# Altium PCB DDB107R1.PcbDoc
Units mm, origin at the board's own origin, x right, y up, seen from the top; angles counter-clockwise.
Board outline 117 x 54.5 mm, 4 copper layers (Top Layer, Layer 1, Layer 2, Bottom Layer); 23 components, 8 nets, 55 pads, 275 vias.
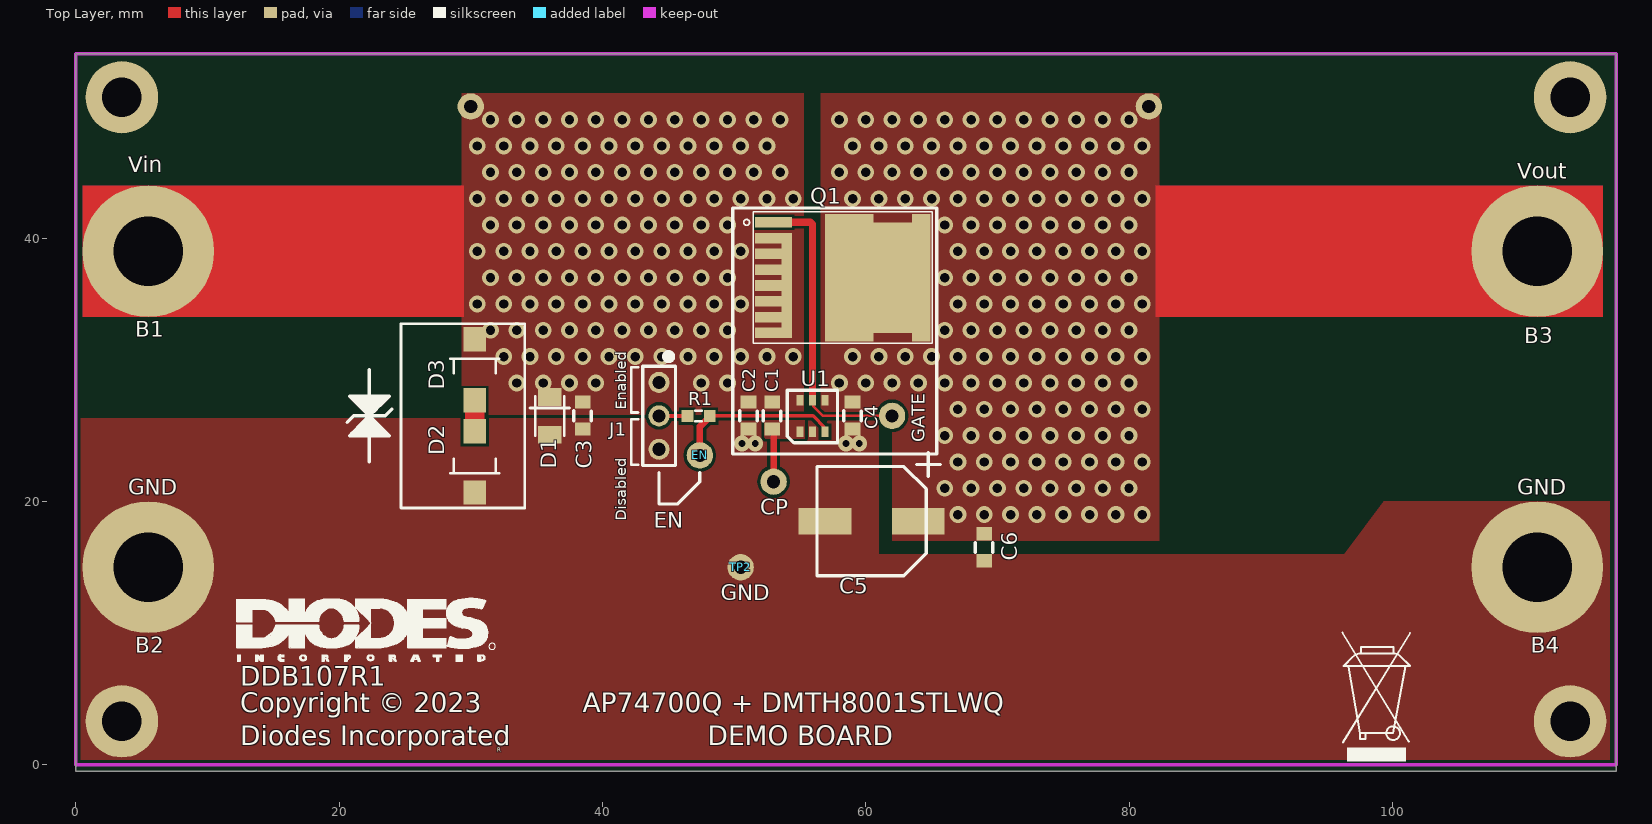
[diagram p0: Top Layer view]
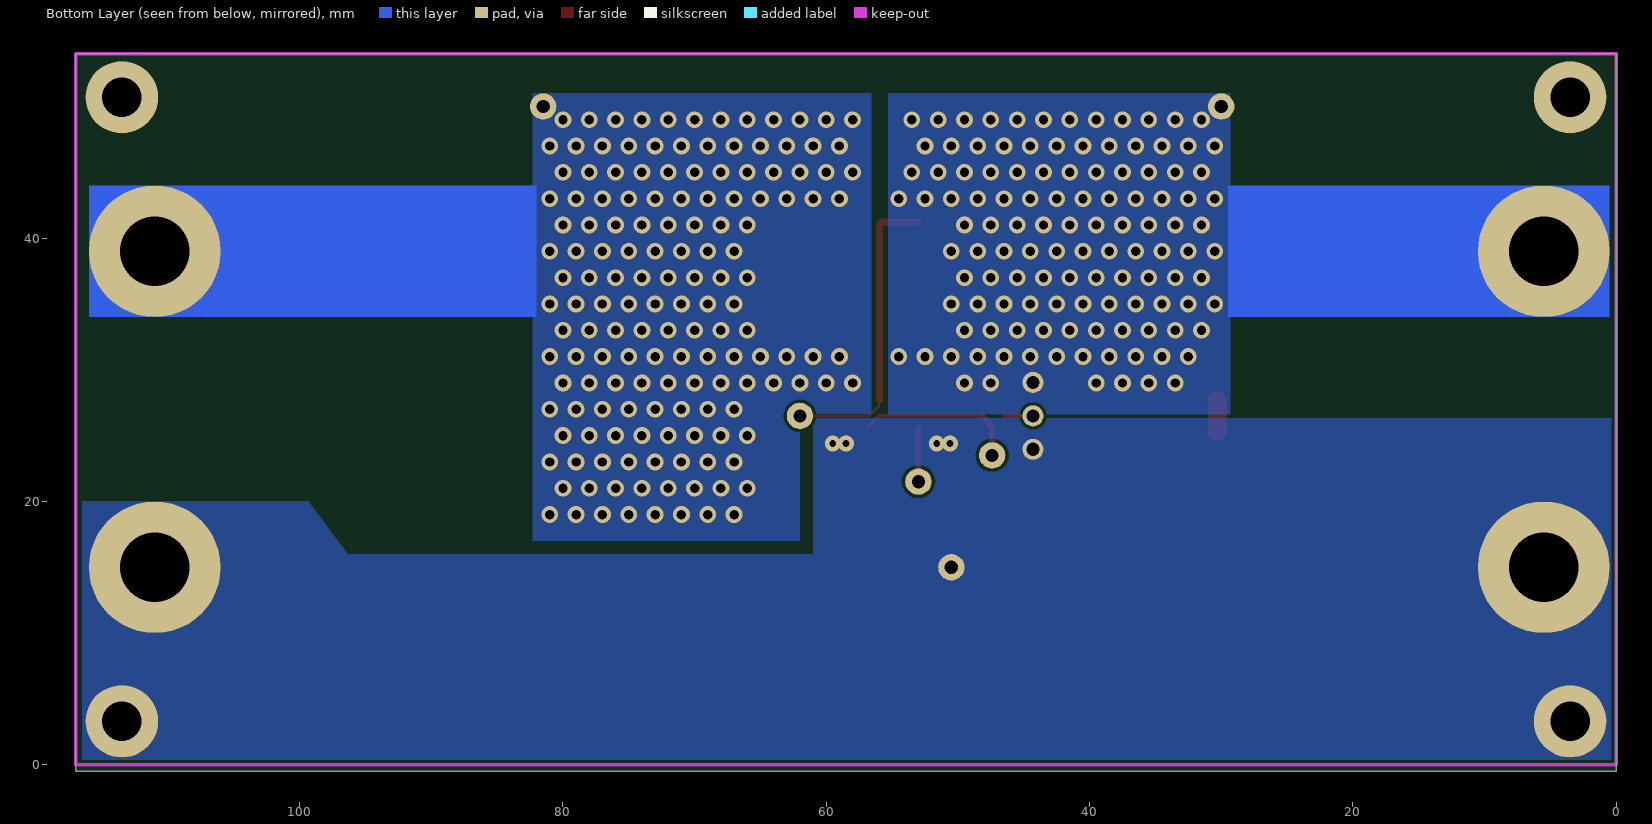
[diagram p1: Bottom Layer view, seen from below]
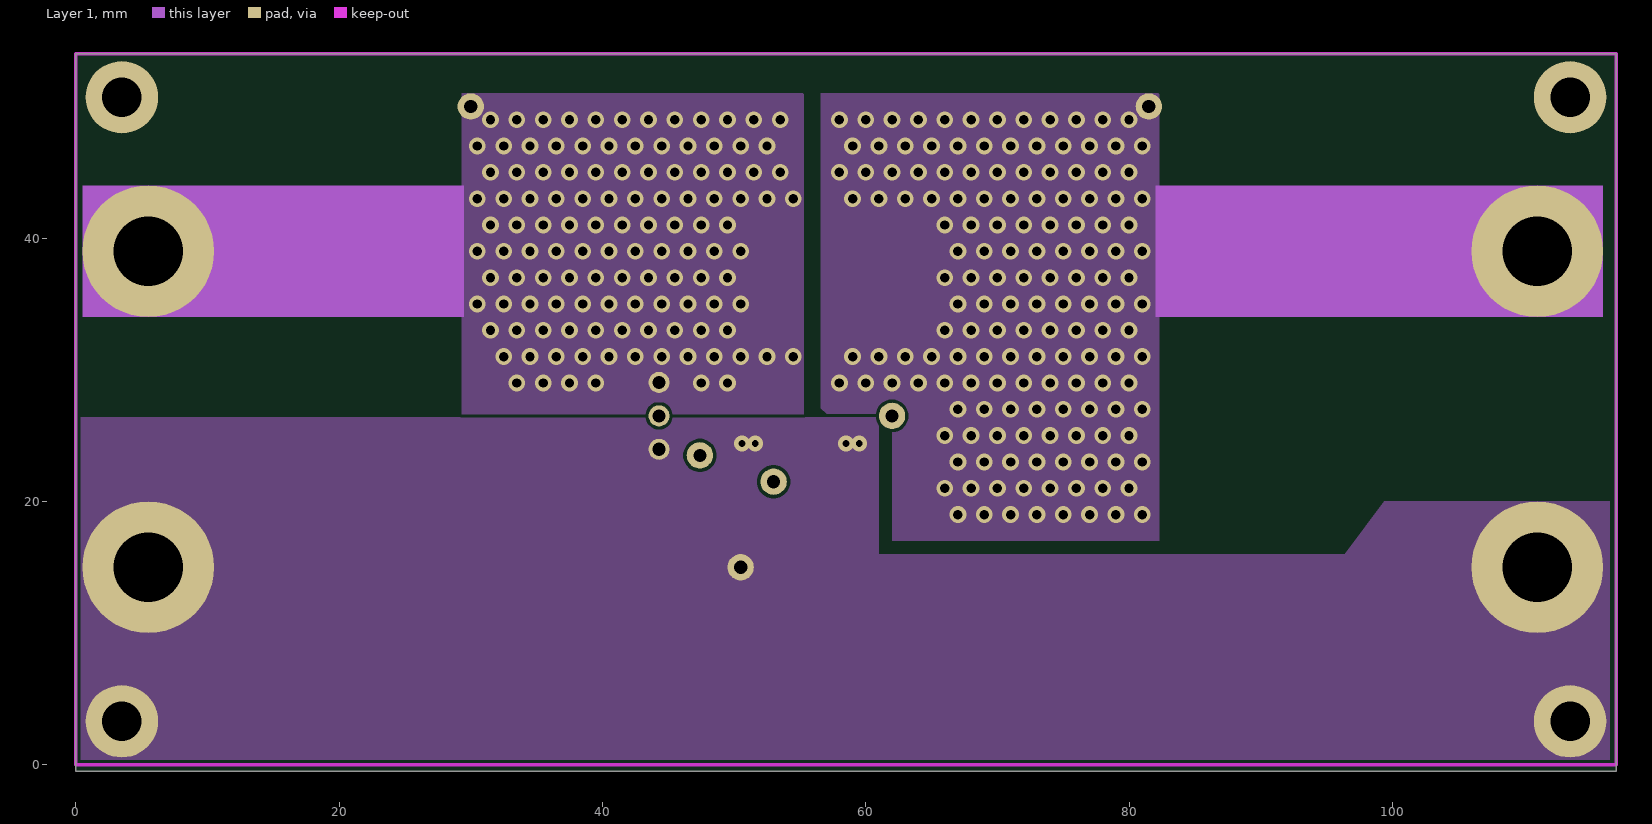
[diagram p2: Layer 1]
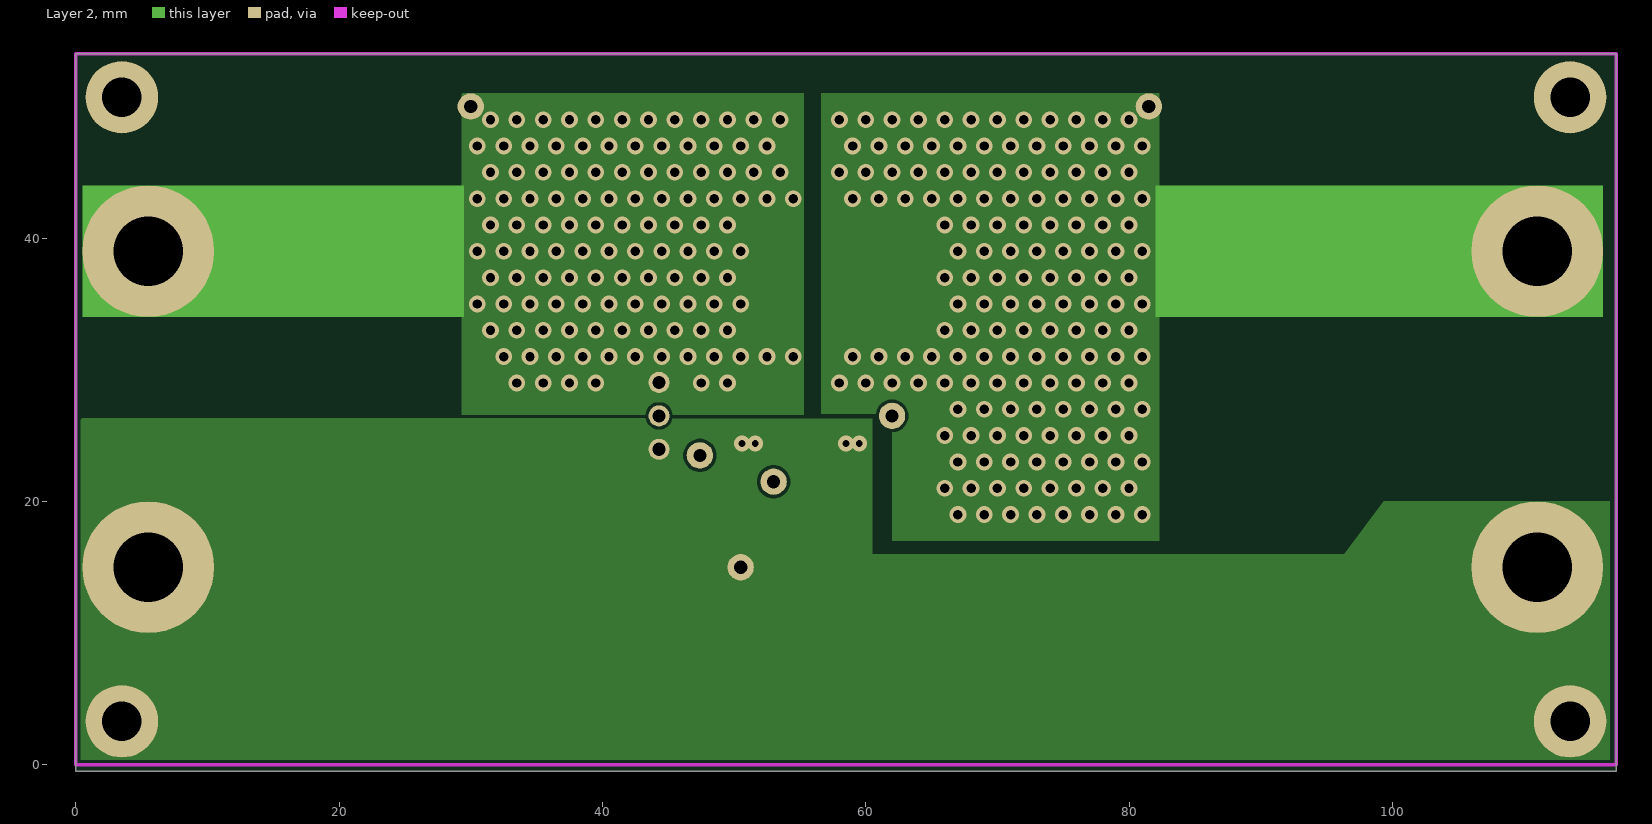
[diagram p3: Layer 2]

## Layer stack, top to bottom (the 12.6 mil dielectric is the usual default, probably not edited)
Top Solder: solder mask 0.0102, Solder Resist, Dk 3.5
Top Layer: signal copper 0.035
Dielectric 1: prepreg 0.32, FR-4, Dk 4.8
Layer 1: signal copper 0.035
Dielectric2: dielectric 0.32, FR-4, Dk 4.8
Layer 2: signal copper 0.035
Dielectric 3: prepreg 0.32, FR-4, Dk 4.8
Bottom Layer: signal copper 0.035
Bottom Solder: solder mask 0.0102, Solder Resist, Dk 3.5

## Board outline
0,54 117,54 117,-0.5 0,-0.5

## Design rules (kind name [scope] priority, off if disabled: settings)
Clearance Clearance_2 [(InNet('GND'))] p1: gap=0.25 ignorepadtopadclearanceinfootprint=FALSE except(0: Arc-Hole Track-Hole SMDPad-Hole THPad-Hole Via-Hole Fill-Hole Poly-Hole Region-Hole Text-Hole)
Clearance Clearance_1 [(IsPad AND OnLayer('Multi-Layer'))] p2: gap=0.25 ignorepadtopadclearanceinfootprint=FALSE except(0: Arc-Hole Track-Hole SMDPad-Hole THPad-Hole Via-Hole Fill-Hole Poly-Hole Region-Hole Text-Hole)
Clearance [All] p3: gap=0.2 ignorepadtopadclearanceinfootprint=FALSE except(0: Arc-Hole Track-Hole SMDPad-Hole THPad-Hole Via-Hole Fill-Hole Poly-Hole Region-Hole Text-Hole)
FabricationTestPointUsage TestPointUsage [All] p1: valid=0 allowmultiple=FALSE
FabricationTestpoint Testpoint [All] p1: side=3 testpointundercomponent=TRUE minsize=1.016 maxsize=2.54 preferedsize=1.524 minholesize=0 maxholesize=1.016 preferedholesize=0.813 testpointgrid=0.025 allowsidetop=TRUE allowsidebottom=TRUE usegrid=TRUE gridtolerance=0
HoleSize [All] p1: absolutevalues=TRUE maxlimit=10 minlimit=0.2 maxpercent=80.000 minpercent=20.000
PlaneClearance [All] p1: clearance=0.1
PolygonConnect [All] p1: connectstyle=Direct reliefconductorwidth=0.254 reliefentries=4 polygonreliefangle="90 Angle" airgapwidth=0.254
RoutingVias [All] p1: holewidth=0.711 width=1.27 viastyle="Through Hole" minholewidth=0.5 minwidth=0.5 maxholewidth=1.5 maxwidth=1.5
SolderMaskExpansion [All] p1: expansion=0.102 istentingtop=FALSE
Width [All] p1: maxlimit=10 minlimit=0.2 preferedwidth=0.254 minimp=50.000000 maximp=50.000000 favimp=50.000000
26 further rules are at their usual default settings.

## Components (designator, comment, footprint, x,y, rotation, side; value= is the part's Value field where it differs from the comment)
B1 "Banana Socket 4mm" "Banana Plug"#1 34,39 r0 top
B2 "Banana Socket 4mm" "Banana Plug"#2 34,14 r0 top
B3 "Banana Socket 4mm" "Banana Plug"#3 78,39 r0 top
B4 "Banana Socket 4mm" "Banana Plug"#4 78,14 r0 top
C1 "Capacitor" 0805 52.9,26.5 r90 top
C2 "Capacitor" 0805 51.1,26.5 r90 top
C3 "Capacitor" 0805 38.5,26.5 r90 top
C4 "Capacitor" 0805 59,26.5 r90 top
C5 "Capacitor" "Case F Cap" 60.45,18.5 r270 top
C6 "Capacitor" 0805 69,16.5 r90 top
CP "Test Point" TestPoint#1 53,21.5 r0 top
D1 "SMF4L30CAQ" SMF4Lxx(C)AQ 36,26.5 r90 top
D2 "P6SMAJ26ADFQ" P6SMAJxxADFQ 30.3,23 r90 top
D3 "P6SMAJ43ADFQ" P6SMAJxxADFQ 30.3,30 r270 top
EN "Test Point" TestPoint#1 47.4,23.5 r0 top
GATE "Test Point" TestPoint#2 58.5,26.5 r90 top
J1 "3W header" "0.1\" 3W" 44.3,26.5 r270 top
Q1 "DMTH8001STLWQ" PowerDI1012-8L 58.25,37 r0 top
R1 "Resistance" 0603 47.3,26.5 r0 top
TP2 "Test Point" TestPoint#1 50.5,15 r90 top
U1 "AP74700" SOT26 56,26.5 r0 top
Vin "Test Point" TestPoint#3 38,50 r90 top
Vout "Test Point" TestPoint#4 74.5,50 r90 top

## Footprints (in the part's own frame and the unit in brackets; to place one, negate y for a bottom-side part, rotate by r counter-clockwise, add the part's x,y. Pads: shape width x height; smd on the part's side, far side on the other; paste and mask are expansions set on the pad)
"0.1\" 3W" [mm]
  round 1.6 hole 1: 1(-2.54,0) 2(0,0) 3(2.54,0)
  silkscreen extent -4.75,-1.25 3.77,1.25, body extent -3.77,-1.25 3.77,1.25, height 8
0603 [mm]
  rect 0.9x0.9 smd: 1(-0.85,0) 2(0.85,0)
  silkscreen extent -0.25,-0.4 0.25,0.4, body extent -1.4,-0.55 1.4,0.55
0805 [mm]
  rect 1x1.2 smd: 1(-1,0) 2(1.05,0)
  silkscreen extent -0.38,-0.65 0.38,0.67, body extent -1.65,-0.7 1.65,0.7
"Banana Plug"#1 [mm]
  round 10 hole 5.3: 1(-28.5,0)
"Banana Plug"#2 [mm]
  round 10 hole 5.3: 1(-28.5,1)
"Banana Plug"#3 [mm]
  round 10 hole 5.3: 1(33,0)
"Banana Plug"#4 [mm]
  round 10 hole 5.3: 1(33,1)
"Case F Cap" [mm]
  rect 2x4 smd: 1(0,3.55) 2(0,-3.55)
  silkscreen extent -5.2,-4.15 4.15,5.2, body extent -4.15,-4.15 4.15,4.15
P6SMAJxxADFQ [mm]
  rect 1.85x1.7 smd: 0(-2.325,0) 1(2.325,0)
  silkscreen extent -0.85,-1.85 0.25,1.85, body extent -2.3,-1.47 2.3,1.47
PowerDI1012-8L [mm]
  rect 2.8x0.8 smd: 1(-5.25,4.2) 2(-5.25,3) 3(-5.25,1.8) 4(-5.25,0.6) 5(-5.25,-0.6) 6(-5.25,-1.8) 7(-5.25,-3) 8(-5.25,-4.2)
  rect 0.8x8 smd: 5(-4.25,-0.6)
  rect 3.7x9.7 smd: 9(0.5,0)
  rect 3.2x8.4 smd: 10(3.75,0)
  rect 1.4x9.7 smd: 11(5.95,0)
  silkscreen extent -7.52,-5 6.8,5
SMF4Lxx(C)AQ [mm]
  rect 1.34x1.8 smd: 0(1.43,0) 1(-1.43,0)
  silkscreen extent -1.5,-1.5 1.5,1.5, body extent -1.45,-1 1.45,1
SOT26 [mm]
  rect 0.55x0.8 smd: 1(-1.002,-1.198) 2(-0.052,-1.198) 3(0.898,-1.198) 4(0.898,1.202) 5(-0.052,1.202) 6(-1.002,1.202)
  silkscreen extent -1.95,-2.05 1.85,1.95, body extent -1.55,-1.4 1.45,1.4
TestPoint#1 [mm]
  round 2 hole 1: 1(0,0)
TestPoint#2 [mm]
  round 2 hole 1: 1(0,-3.5)
TestPoint#3 [mm]
  round 2 hole 1: 1(0,8)
TestPoint#4 [mm]
  round 2 hole 1: 1(0,-7)

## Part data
D1: library part SMF4Lxx(C)AQ, "TVS Device"
D2 D3: library part P6SMAJxxADFQ, "TVS Device"
Q1: library part PowerDI1012-8L

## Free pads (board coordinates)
  round 5.5 hole 3: 0(3.5,3.3) 0(3.5,50.7) 0(113.5,3.3) 0(113.5,50.7)

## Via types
v1: diameter 1.27, hole 0.711, Top Layer to Bottom Layer, 271 vias
v2: diameter 1.2, hole 0.5, Top Layer to Bottom Layer, tented both sides, 4 vias

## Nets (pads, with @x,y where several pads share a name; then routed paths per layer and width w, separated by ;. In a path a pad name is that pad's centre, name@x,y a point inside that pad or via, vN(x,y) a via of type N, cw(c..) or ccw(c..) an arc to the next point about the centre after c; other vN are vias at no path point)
GND: B2.1 B4.1 C2.1 C3.1 C4.1 C5.2 C6.1 D1.1 D2.0 J1.3 pad.0@3.5,3.3 pad.0@113.5,3.3 TP2.1 U1.2
  other v2: 50.6,24.4 51.6,24.4 58.5,24.4 59.5,24.4
NetC1_1: C1.1 CP.1 U1.1 | length 4
  Top Layer w0.5: CP.1 C1.1@53,25.5
NetD2_1: D2.1 D3.1 | length 2.4
  Top Layer w1.5: D2.1 D3.1
NetEN_1: EN.1 R1.2 U1.3 | length 12.4
  Top Layer w0.25: R1.2@48.2,26.5 56,26.5 U1.3@56.899,25.602
  Top Layer w0.5: EN.1 47.4,25.7 R1.2@48.2,26.5
NetGATE_1: GATE.1 Q1.1 U1.5 | length 22.8
  Top Layer w0.2: U1.5@56,27.4 56,27.25 56.75,26.5 GATE.1
  Top Layer w0.55: Q1.1 55.8,41.2 55.949,41.052 U1.5
NetJ1_2: J1.2 R1.1 | length 2.2
  Top Layer w0.3: J1.2 R1.1@46.5,26.5
VIN: B1.1 C1.2 C2.2 C3.2 D1.0 D3.0 J1.1 Q1.2 Q1.3 Q1.4 Q1.5 Q1.6 Q1.7 Q1.8 U1.6 Vin.1
  other v1: 33.5,29 35.5,29 37.5,29 39.5,29 47.5,29 49.5,29 32.5,31 34.5,31 36.5,31 38.5,31 40.5,31 42.5,31 44.5,31 46.5,31 48.5,31 50.5,31 52.5,31 54.5,31 31.5,33 33.5,33 35.5,33 37.5,33 39.5,33 41.5,33 43.5,33 45.5,33 47.5,33 49.5,33 30.5,35 32.5,35 34.5,35 36.5,35 38.5,35 40.5,35 42.5,35 44.5,35 46.5,35 48.5,35 50.5,35 31.5,37 33.5,37 35.5,37 37.5,37 39.5,37 41.5,37 43.5,37 45.5,37 47.5,37 49.5,37 30.5,39 32.5,39 34.5,39 36.5,39 38.5,39 40.5,39 42.5,39 44.5,39 46.5,39 48.5,39 50.5,39 31.5,41 33.5,41 35.5,41 37.5,41 39.5,41 41.5,41 43.5,41 45.5,41 47.5,41 49.5,41 30.5,43 32.5,43 34.5,43 36.5,43 38.5,43 40.5,43 42.5,43 44.5,43 46.5,43 48.5,43 50.5,43 52.5,43 54.5,43 31.5,45 33.5,45 35.5,45 37.5,45 39.5,45 41.5,45 43.5,45 45.5,45 47.5,45 49.5,45 51.5,45 53.5,45 30.5,47 32.5,47 34.5,47 36.5,47 38.5,47 40.5,47 42.5,47 44.5,47 46.5,47 48.5,47 50.5,47 52.5,47 31.5,49 33.5,49 35.5,49 37.5,49 39.5,49 41.5,49 43.5,49 45.5,49 47.5,49 49.5,49 51.5,49 53.5,49
VOUT: B3.1 C4.2 C5.1 C6.2 Q1.9 Q1.10 Q1.11 U1.4 Vout.1
  other v1: 67,19 69,19 71,19 73,19 75,19 77,19 79,19 81,19 66,21 68,21 70,21 72,21 74,21 76,21 78,21 80,21 67,23 69,23 71,23 73,23 75,23 77,23 79,23 81,23 66,25 68,25 70,25 72,25 74,25 76,25 78,25 80,25 67,27 69,27 71,27 73,27 75,27 77,27 79,27 81,27 58,29 60,29 62,29 64,29 66,29 68,29 70,29 72,29 74,29 76,29 78,29 80,29 59,31 61,31 63,31 65,31 67,31 69,31 71,31 73,31 75,31 77,31 79,31 81,31 66,33 68,33 70,33 72,33 74,33 76,33 78,33 80,33 67,35 69,35 71,35 73,35 75,35 77,35 79,35 81,35 66,37 68,37 70,37 72,37 74,37 76,37 78,37 80,37 67,39 69,39 71,39 73,39 75,39 77,39 79,39 81,39 66,41 68,41 70,41 72,41 74,41 76,41 78,41 80,41 59,43 61,43 63,43 65,43 67,43 69,43 71,43 73,43 75,43 77,43 79,43 81,43 58,45 60,45 62,45 64,45 66,45 68,45 70,45 72,45 74,45 76,45 78,45 80,45 59,47 61,47 63,47 65,47 67,47 69,47 71,47 73,47 75,47 77,47 79,47 81,47 58,49 60,49 62,49 64,49 66,49 68,49 70,49 72,49 74,49 76,49 78,49 80,49

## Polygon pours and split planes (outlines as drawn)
GND on Top Layer "Top Layer-No Net" (solid, pour order 1004): 0,26.3 0,-0.105 116.5,-0.105 116.5,20 99.349,20 96.349,16 61,16 61,26.3
VIN on Top Layer "Top Layer-No Net" (solid, pour order 1003): 55.304,26.6 29.3,26.6 29.3,51 55.304,51
VOUT on Top Layer "Top Layer-No Net" (solid, pour order 1002): 56.6,26.65 56.6,51 82.3,51 82.3,17 62,17 62,26.65
NetC1_1 on Top Layer "Top Layer-No Net" (solid, pour order 1001): 55.375,26.2 52.3,26.2 52.3,24.775 55.375,24.775
GND on Bottom Layer "Top Layer-No Net" (solid, pour order 1005): 0,26.3 61,26.3 61,16 96.327,16 99.327,20 116.5,20 116.5,-0.116 0,-0.116
VIN on Bottom Layer "NONET_L-01_P-001" (solid, pour order 1016): 29.3,51 55.296,51 55.296,26.608 29.3,26.608
VOUT on Bottom Layer "NONET_L-01_P-001" (solid, pour order 1017): 56.594,51 82.3,51 82.3,17 62,17 62,26.655 56.594,26.655
VOUT on Layer 1 "NONET_L-01_P-001" (solid, pour order 1009): 56.595,50.998 82.3,51.005 82.3,17 62,17 62,26.653 57.028,26.653 56.595,27.087
VIN on Layer 1 "NONET_L-01_P-001" (solid, pour order 1010): 29.3,50.995 55.3,51.001 55.3,26.608 29.3,26.608
GND on Layer 1 "NONET_L-01_P-001" (solid, pour order 1011): 0,26.384 61,26.405 61,16 96.367,16 99.367,20 116.5,20 116.5,-0.13 0,-0.13
VIN on Layer 2 "NONET_L-01_P-001" (solid, pour order 1012): 29.3,51.001 29.3,26.6 55.304,26.6 55.304,50.997
VOUT on Layer 2 "NONET_L-01_P-001" (solid, pour order 1013): 56.615,51 56.615,26.651 62,26.651 62,17 82.3,17 82.3,51
GND on Layer 2 "NONET_L-01_P-001" (solid, pour order 1014): -0.5,26.308 -0.5,-0.101 116.5,-0.101 116.5,20 99.355,20 96.355,16 60.5,16 60.5,26.298

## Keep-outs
Keep-Out Layer:
  lines w0.254: 0,0 117,0 117,54 0,54 0,0

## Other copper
Top Layer:
  rectangle net VOUT: 82,34 116,44
  rectangle net VIN: 0.5,34 29.5,44
Layer 1:
  rectangle net VOUT: 82,34 116,44
  rectangle net VIN: 0.5,34 29.5,44
Layer 2:
  rectangle net VOUT: 82,34 116,44
  rectangle net VIN: 0.5,34 29.5,44
Bottom Layer:
  rectangle net VOUT: 82,34 116,44
  rectangle net VIN: 0.5,34 29.5,44

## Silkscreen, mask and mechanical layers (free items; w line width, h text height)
Top Overlay:
  drawing of 484 lines, arcs and shapes, not listed
  text "Enabled" at 41.804,26.951 h0.8 r90
  text "GND" at 4,20.5 h1.2
  text "GND" at 109.5,20.5 h1.2
  text "Disabled" at 41.819,18.538 h0.8 r90
  text "EN" at 43.9,18 h1.2
  text "GND" at 49,12.5 h1.2
  text "DDB107R1" at 12.5,5.5 h2.5
  text "Copyright © 2023" at 12.5,3.5 h2.5
  text "AP74700Q + DMTH8001STLWQ" at 38.5,3.5 h2.5
  text "Diodes Incorporated" at 12.5,1 h2.5
  text "DEMO BOARD" at 48,1 h2.5
  text "R" at 32.025,0.865 h0.5
Mechanical 1:
  text "A)      THE CONTROLLING UNIT IS MILLIMETRES" at 95,127 h1.8
  text "B)      THE BOARD MUST BE ROHS COMPLIANT" at 95,123 h1.8
  text "C)      MATERIAL : LAMINATED SHEET COPPERCLAD TYPE FR-4 OR EQUIVALENT" at 95,119 h1.8
  text "2 LAYERS TO BE 1 OZ NOMINAL WITH 1.6MM TOTAL BOARD THICKNESS." at 110,115 h1.8
  text "D)      REMOVE ALL BURRS AND SHARP EDGES" at 95,111 h1.8
  text "E)      FINISH COAT ALL EXPOSED EXTERNAL COPPER WITH TIN" at 95,107 h1.8
  text "F)      SILKSCREEN USING WHITE NON-CONDUCTIVE INK" at 95,103 h1.8
  text "REGISTRATION WITH PWB MUST BE +/- 0.125MM" at 110,99 h1.8
  text "G)      SOLDERMASK: APPLY BOTH SIDES" at 95,95 h1.8
  text "Layer List:" at 95,87 h1.8
  text "Top Silk" at 95,83 h1.8
  text "Top Solder" at 95,79 h1.8
  text "Top Copper" at 95,75 h1.8
  text "Top Paste" at 95,71 h1.8
  text "Bottom Copper" at 95,67 h1.8
  text "Bottom Solder" at 95,63 h1.8
  text "Mech 4 (Edge)" at 95,59 h1.8
  text "Mech 1 (Instructions)" at 95,55 h1.8
Mechanical 4:
  lines w0.2: 0,0 117,0 117,54 0,54 0,0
